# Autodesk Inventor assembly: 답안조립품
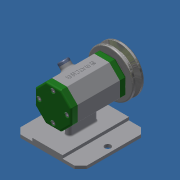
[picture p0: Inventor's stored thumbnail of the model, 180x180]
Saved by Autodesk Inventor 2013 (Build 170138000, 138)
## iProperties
Created: 2018-06
Part Number: 답안조립품
Document SubType Name: Assembly
Designer: Administrator
Author: Administrator
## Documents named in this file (16)
- C:\Users\Administrator\Desktop\480607V1007\답안조립품.iam
- C:\Users\Administrator\Desktop\480607V1007\본체.ipt
- C:\Users\Administrator\Desktop\480607V1007\베어링 15x32x9.ipt
- C:\Users\Administrator\Desktop\480607V1007\뒤커버.ipt
- C:\Users\Administrator\Desktop\480607V1007\앞커버.ipt
- C:\Users\Administrator\Desktop\480607V1007\오일 실 15 25 7.ipt
- C:\Users\Administrator\Desktop\480607V1007\V벨트풀리.ipt
- C:\Users\Administrator\Desktop\480607V1007\고무캡.ipt
- C:\Users\Administrator\Desktop\480607V1007\스프링와셔 8.ipt
- C:\Users\Administrator\Desktop\480607V1007\와셔 8x17.ipt
- C:\Users\Administrator\Desktop\480607V1007\축.ipt
- C:\Users\Administrator\Desktop\480607V1007\키 3x3x12.ipt
- 키 3x3x12.ipt
- C:\Users\Administrator\Desktop\480607V1007\너트 M8.ipt
- 너트 M8.ipt
- C:\Users\Administrator\Desktop\480607V1007\볼트 M4x12.ipt
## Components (2 placed, 2 different names)
1. V벨트풀리:1
2. 고무캡:1
